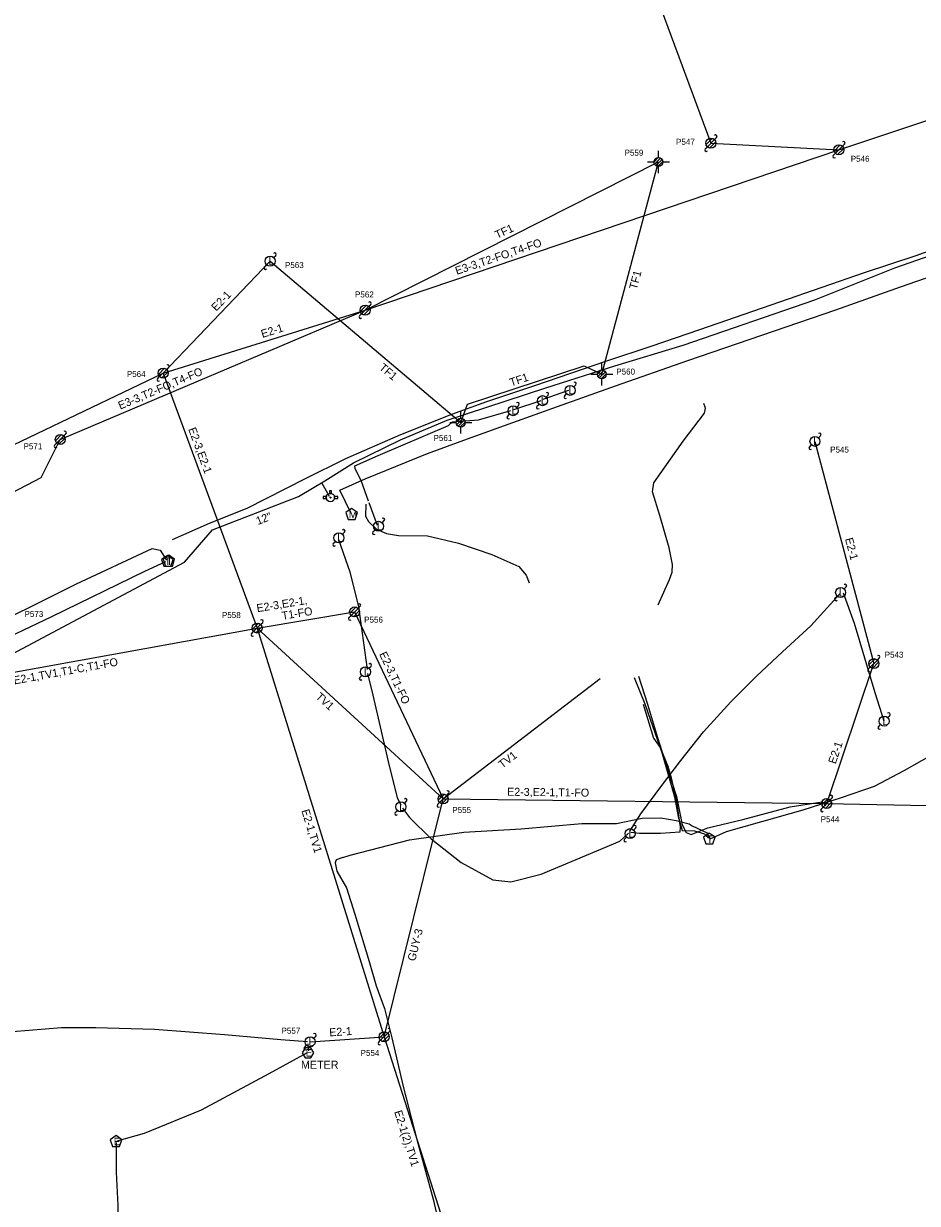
# Model space of a CAD drawing. Extents: x 1614474 to 1865144, y 1098877 to 1212550.
# Drawn here: x 1812913 to 1813359, y 1189432 to 1190021 of the extents above; entities that cross this region are included whole.
import ezdxf

# ---------------------------------------------------------------- set-up
doc = ezdxf.new("R2010")
doc.units = 0
for name, color, linetype in [('RD_EX_SU_Elec', 7, 'Continuous'), ('RD_EX_SU_H2O', 7, 'Continuous'), ('RD_EX_SU_Ovhd', 7, 'Continuous'), ('RD_EX_SU_Pole', 7, 'Continuous'), ('RD_EX_SU_Telecom', 7, 'Continuous'), ('RD_EX_SU_TX_Elec', 7, 'Continuous'), ('RD_EX_SU_TX_H2O', 7, 'Continuous'), ('RD_EX_SU_TX_Pole', 7, 'Continuous')]:
    doc.layers.add(name, color=color, linetype=linetype)

# ---------------------------------------------------------------- blocks, each defined once
blk = doc.blocks.new('SUE_PP')
at = {"layer": 'RD_EX_SU_Pole'}
for p, q in [((-2.41, -0.65), (0.65, 2.41)), ((-1.77, -1.77), (1.77, 1.77)), ((-0.65, -2.41), (2.41, 0.65)), ((1.77, 1.77), (2.83, 2.83)), ((-2.83, -2.83), (-1.77, -1.77))]:
    blk.add_line(p, q, dxfattribs=at)
blk.add_circle((0, 0), 2.5, dxfattribs=at)
for centre, start, end in [((2.3, 3.36), 315, 135), ((-2.3, -3.36), 135, 315)]:
    blk.add_arc(centre, 0.75, start, end, dxfattribs=at)
blk = doc.blocks.new('SUE_TPP')
at = {"layer": 'RD_EX_SU_Telecom'}
blk.add_lwpolyline([(0, 3), (-2.85, 0.93), (-1.76, -2.43), (1.76, -2.43), (2.85, 0.93)], close=True, dxfattribs=at)
blk.add_text('T', height=3.75, dxfattribs=at).set_placement((-1.25, -1.88))
blk = doc.blocks.new('SUE_WFH')
at = {"layer": 'RD_EX_SU_H2O'}
for p, q in [((-2.01, 0.6), (-3.65, 0.6)), ((-3.65, 0.6), (-3.65, -0.45)), ((-0.48, 3.38), (-0.48, 2.04)), ((0.57, 3.38), (-0.48, 3.38)), ((0.57, 2.02), (0.57, 3.38)), ((3.7, 0.6), (2.01, 0.6)), ((3.7, -0.45), (3.7, 0.6)), ((-3.65, -0.45), (-2.05, -0.45)), ((2.05, -0.45), (3.7, -0.45))]:
    blk.add_line(p, q, dxfattribs=at)
for radius in [2.1, 0.263]:
    blk.add_circle((0, 0), radius, dxfattribs=at)
for start, end in [(163.3387, 192.31502), (74.24552, 103.21276), (347.68498, 16.6613)]:
    blk.add_arc((0, 0), 2.1, start, end, dxfattribs=at)
blk = doc.blocks.new('SUE_WM')
at = {"layer": 'RD_EX_SU_H2O'}
blk.add_lwpolyline([(0, 3.05), (-2.9, 0.94), (-1.79, -2.47), (1.79, -2.47), (2.9, 0.94)], close=True, dxfattribs=at)
blk.add_text('M', height=3.75, dxfattribs=at).set_placement((-1.43, -1.88))

msp = doc.modelspace()

# ---------------------------------------------------------------- linework, layer by layer
at = {"layer": 'RD_EX_SU_Elec'}
for p, q in [((1813172.2, 1189833.77), (1813184.99, 1189838.24)), ((1813157.49, 1189828.68), (1813171.11, 1189833.14)), ((1813084.97, 1189782.12), (1813089.24, 1189770.86)), ((1813054.52, 1189511.62), (1813054.88, 1189508.19))]:
    msp.add_line(p, q, dxfattribs=at)
for points in [[(1813084.8, 1189782.72), (1813081.16, 1189793.2), (1813078.24, 1189799.02), (1813078.11, 1189800.47), (1813089.66, 1189805.56), (1813124.92, 1189820.6), (1813126.88, 1189822.42), (1813139.84, 1189823.39), (1813156.03, 1189828.18)], [(1813229.62, 1189731.04), (1813235.19, 1189743.69), (1813236.63, 1189747.25), (1813236.84, 1189751.08), (1813235.18, 1189759.44), (1813230.46, 1189775.63), (1813226.78, 1189787.46), (1813227.5, 1189791.98), (1813242.03, 1189812.74), (1813252.8, 1189826.76), (1813253.21, 1189829.19), (1813252.42, 1189831.68)], [(1813083.58, 1189781.3), (1813083.29, 1189775.35), (1813084.79, 1189772.68), (1813088.83, 1189768.74), (1813093.82, 1189766.63), (1813099.9, 1189765.58), (1813114.37, 1189765.46), (1813129.83, 1189761.79), (1813146.53, 1189756.21), (1813159.94, 1189750.16), (1813163.6, 1189745.85), (1813165.14, 1189741.93)], [(1813069.9, 1189763.7), (1813075.59, 1189747.53), (1813079.94, 1189730.01), (1813082.4, 1189712.02), (1813084.12, 1189698.67)], [(1813215.48, 1189617.9), (1813220.92, 1189626.65), (1813231.43, 1189640.69), (1813240.87, 1189653.16), (1813252.21, 1189667.55), (1813265.87, 1189682.5), (1813278.75, 1189695.4), (1813291.8, 1189707.54), (1813305.86, 1189720.44), (1813320.47, 1189736.69)], [(1813322.09, 1189736.98), (1813327.51, 1189721.81), (1813337.79, 1189687.25), (1813342.36, 1189673.09)], [(1813084.31, 1189696.75), (1813087, 1189685.89), (1813091.12, 1189667.82), (1813095.19, 1189650.6), (1813099.16, 1189634.7), (1813100.95, 1189630.93)], [(1813219.74, 1189695.38), (1813224.14, 1189681.94), (1813229.28, 1189664.63), (1813234.01, 1189650.08), (1813238.7, 1189635.2), (1813241.53, 1189621), (1813243.55, 1189617.16), (1813246.01, 1189616.2), (1813254.4, 1189619.51), (1813271.84, 1189623.68), (1813295.49, 1189630.04), (1813311.6, 1189632.56), (1813313.32, 1189630.61)], [(1813222.12, 1189681.31), (1813227.35, 1189664.46), (1813230.57, 1189659.71), (1813234.5, 1189650.34), (1813236.05, 1189644.54), (1813238.7, 1189632.16), (1813240.56, 1189620.13), (1813240.51, 1189617.37), (1813230.72, 1189616.67), (1813220.31, 1189616.77), (1813215.93, 1189617.17)], [(1813101.94, 1189629.37), (1813105.36, 1189624.7), (1813116.25, 1189614.02), (1813131.09, 1189602.33), (1813146.98, 1189593.61), (1813156.06, 1189592.63), (1813171.1, 1189596.36), (1813199.01, 1189608.09), (1813210.42, 1189612.97), (1813214.78, 1189616.97)], [(1812867.17, 1189511.33), (1812869.82, 1189511.09), (1812890.43, 1189516.51), (1812931.39, 1189519.83), (1812948.66, 1189519.83), (1812977.88, 1189518.89), (1813012.86, 1189516.32), (1813041.01, 1189513.73), (1813054.44, 1189512.83)], [(1812959.31, 1189463.15), (1812972.97, 1189467.02), (1813001.48, 1189478.6), (1813035.3, 1189496.77), (1813054.4, 1189507.35)], [(1812958.79, 1189462.41), (1812958.8, 1189447.44), (1812959.6, 1189430.8), (1812958.07, 1189367), (1812957.55, 1189348.86), (1812956.38, 1189299.52), (1812957.5, 1189269.31), (1812955.97, 1189255.72), (1812952.75, 1189234.62)]]:
    msp.add_lwpolyline(points, dxfattribs=at)
for points in [[(1813057.55, 1189507.16), (1813056.11, 1189509.66), (1813053.22, 1189509.66), (1813051.78, 1189507.16), (1813053.22, 1189504.66), (1813056.11, 1189504.66)], [(1812958.73, 1189465.85), (1812955.83, 1189463.74), (1812956.93, 1189460.33), (1812960.52, 1189460.33), (1812961.63, 1189463.74)]]:
    msp.add_lwpolyline(points, close=True, dxfattribs=at)
at = {"layer": 'RD_EX_SU_H2O'}
msp.add_line((1813061.4, 1189792.09), (1813065.25, 1189785.38), dxfattribs=at)
for points in [[(1813049.93, 1189785.18), (1813062.98, 1189793.04), (1813077.41, 1189801.91), (1813100.8, 1189813.52), (1813124.24, 1189823.21), (1813173.48, 1189839.48), (1813207.95, 1189850.5), (1813242.12, 1189860.74), (1813307.93, 1189883.34), (1813347.93, 1189899.33), (1813402.79, 1189918.54), (1813471.7, 1189944.89), (1813528.83, 1189966.2), (1813605.69, 1189995.43), (1813667.12, 1190020.2)], [(1813076.17, 1189776.71), (1813070.48, 1189788.22), (1813083.19, 1189794.03), (1813114.42, 1189806.57), (1813134.39, 1189813.94), (1813156.92, 1189822.09), (1813179.27, 1189830.15), (1813208.26, 1189840.49), (1813244.46, 1189853.13), (1813287.8, 1189867.84), (1813318.33, 1189878.33), (1813350.77, 1189889.9), (1813379.04, 1189899.78), (1813403.28, 1189907.87), (1813412.45, 1189891.9), (1813420.34, 1189875.71), (1813427, 1189862.13)], [(1812530.07, 1189435.57), (1812805.53, 1189652.49), (1812993.01, 1189752.31), (1813006.84, 1189768.49), (1813049.93, 1189785.18)]]:
    msp.add_lwpolyline(points, dxfattribs=at)
at = {"layer": 'RD_EX_SU_Ovhd'}
for p, q in [((1813205.47, 1190098.07), (1813255.96, 1189961.68)), ((1813319.93, 1189958.41), (1813557.25, 1190037.52)), ((1813083.19, 1189878.25), (1813319.93, 1189958.41)), ((1813255.96, 1189961.68), (1813319.93, 1189958.41)), ((1813083.19, 1189878.25), (1813229.74, 1189952.29)), ((1813201.45, 1189846.2), (1813229.74, 1189952.29)), ((1812982.29, 1189846.79), (1813035.7, 1189902.73)), ((1813035.7, 1189902.73), (1813130.96, 1189822.07)), ((1812930.87, 1189813.64), (1813083.19, 1189878.25)), ((1812982.29, 1189846.79), (1813083.19, 1189878.25)), ((1812808.56, 1189763.74), (1812982.29, 1189846.79)), ((1812982.29, 1189846.79), (1813029.22, 1189719.4)), ((1813307.96, 1189812.69), (1813337.35, 1189701.63)), ((1813029.22, 1189719.4), (1813077.95, 1189727.45)), ((1813077.95, 1189727.45), (1813122.17, 1189634)), ((1812850.33, 1189686.85), (1813029.22, 1189719.4)), ((1813029.22, 1189719.4), (1813122.17, 1189634)), ((1813029.22, 1189719.4), (1813092.68, 1189515.17)), ((1813313.8, 1189631.73), (1813337.35, 1189701.63)), ((1813122.17, 1189634), (1813200.58, 1189694.11)), ((1813092.68, 1189515.17), (1813122.17, 1189634)), ((1813122.17, 1189634), (1813313.8, 1189631.73)), ((1813313.8, 1189631.73), (1813457.23, 1189628.94)), ((1813055.69, 1189512.68), (1813092.68, 1189515.17)), ((1813092.68, 1189515.17), (1813158.57, 1189308.63))]:
    msp.add_line(p, q, dxfattribs=at)
for points in [[(1813130.96, 1189822.07), (1813134.32, 1189831.24), (1813192.68, 1189850.48), (1813201.45, 1189846.2)], [(1812780.79, 1189733.02), (1812803.04, 1189732.83), (1812921.31, 1189794.68), (1812930.87, 1189813.64)]]:
    msp.add_lwpolyline(points, dxfattribs=at)
at = {"layer": 'RD_EX_SU_Pole'}
for p, q in [((1813253.55, 1189961.03), (1813256.61, 1189964.09)), ((1813254.2, 1189959.91), (1813257.73, 1189963.44)), ((1813257.73, 1189963.44), (1813258.79, 1189964.5)), ((1813229.74, 1189954.51), (1813229.74, 1189957.82)), ((1813253.13, 1189958.85), (1813254.2, 1189959.91)), ((1813255.32, 1189959.26), (1813258.38, 1189962.32)), ((1813317.52, 1189957.76), (1813320.58, 1189960.83)), ((1813318.17, 1189956.64), (1813321.7, 1189960.18)), ((1813319.29, 1189956), (1813322.35, 1189959.06)), ((1813321.7, 1189960.18), (1813322.76, 1189961.24)), ((1813224.22, 1189952.29), (1813227.53, 1189952.29)), ((1813227.53, 1189952.43), (1813229.62, 1189954.5)), ((1813227.78, 1189951.26), (1813230.78, 1189954.25)), ((1813228.43, 1189950.5), (1813231.54, 1189953.6)), ((1813229.44, 1189950.1), (1813231.94, 1189952.59)), ((1813231.96, 1189952.29), (1813235.27, 1189952.29)), ((1813317.11, 1189955.58), (1813318.17, 1189956.64)), ((1813229.74, 1189946.76), (1813229.74, 1189950.07)), ((1813037.47, 1189904.49), (1813038.53, 1189905.56)), ((1813032.87, 1189899.9), (1813033.93, 1189900.96)), ((1813080.77, 1189877.6), (1813083.83, 1189880.66)), ((1813084.95, 1189880.02), (1813086.01, 1189881.08)), ((1813080.36, 1189875.42), (1813081.42, 1189876.48)), ((1813081.42, 1189876.48), (1813084.95, 1189880.02)), ((1813082.54, 1189875.83), (1813085.6, 1189878.89)), ((1813201.45, 1189848.42), (1813201.45, 1189851.73)), ((1812979.87, 1189846.15), (1812982.93, 1189849.21)), ((1812980.52, 1189845.03), (1812984.05, 1189848.56)), ((1812981.64, 1189844.38), (1812984.7, 1189847.44)), ((1812984.05, 1189848.56), (1812985.11, 1189849.62)), ((1813195.93, 1189846.2), (1813199.24, 1189846.2)), ((1813199.24, 1189846.34), (1813201.33, 1189848.42)), ((1813199.49, 1189845.17), (1813202.49, 1189848.16)), ((1813200.14, 1189844.41), (1813203.25, 1189847.51)), ((1813201.15, 1189844.01), (1813203.65, 1189846.5)), ((1813203.67, 1189846.2), (1813206.98, 1189846.2)), ((1812979.46, 1189843.97), (1812980.52, 1189845.03)), ((1813187.4, 1189839.93), (1813188.46, 1189840.99)), ((1813201.45, 1189840.68), (1813201.45, 1189843.99)), ((1813173.61, 1189834.79), (1813174.67, 1189835.85)), ((1813182.81, 1189835.33), (1813183.87, 1189836.39)), ((1813130.96, 1189824.28), (1813130.96, 1189827.59)), ((1813158.89, 1189829.76), (1813159.95, 1189830.83)), ((1813169.01, 1189830.2), (1813170.07, 1189831.26)), ((1813125.44, 1189822.07), (1813128.75, 1189822.07)), ((1813128.75, 1189822.2), (1813130.84, 1189824.28)), ((1813129, 1189821.04), (1813132, 1189824.03)), ((1813129.66, 1189820.28), (1813132.76, 1189823.37)), ((1813130.66, 1189819.87), (1813133.16, 1189822.36)), ((1813133.18, 1189822.07), (1813136.49, 1189822.07)), ((1813154.29, 1189825.17), (1813155.35, 1189826.23)), ((1812928.45, 1189813), (1812931.51, 1189816.06)), ((1812932.64, 1189815.41), (1812933.7, 1189816.47)), ((1813130.96, 1189816.54), (1813130.96, 1189819.85)), ((1812928.04, 1189810.81), (1812929.1, 1189811.87)), ((1812929.1, 1189811.87), (1812932.64, 1189815.41)), ((1812930.22, 1189811.23), (1812933.28, 1189814.29)), ((1813305.14, 1189809.86), (1813306.2, 1189810.92)), ((1813309.73, 1189814.46), (1813310.79, 1189815.52)), ((1813087.09, 1189767.42), (1813088.15, 1189768.48)), ((1813091.68, 1189772.01), (1813092.74, 1189773.07)), ((1813067.26, 1189761.66), (1813068.32, 1189762.72)), ((1813071.86, 1189766.26), (1813072.92, 1189767.32)), ((1813322.55, 1189738.94), (1813323.61, 1189740)), ((1813317.95, 1189734.35), (1813319.01, 1189735.41)), ((1813075.54, 1189726.8), (1813078.6, 1189729.86)), ((1813076.18, 1189725.68), (1813079.72, 1189729.22)), ((1813077.3, 1189725.04), (1813080.37, 1189728.1)), ((1813079.72, 1189729.22), (1813080.78, 1189730.28)), ((1813026.8, 1189718.75), (1813029.86, 1189721.82)), ((1813030.98, 1189721.17), (1813032.04, 1189722.23)), ((1813075.12, 1189724.62), (1813076.18, 1189725.68)), ((1813026.39, 1189716.57), (1813027.45, 1189717.63)), ((1813027.45, 1189717.63), (1813030.98, 1189721.17)), ((1813028.57, 1189716.99), (1813031.63, 1189720.05)), ((1813085.1, 1189699.3), (1813086.16, 1189700.36)), ((1813080.5, 1189694.7), (1813081.56, 1189695.76)), ((1813344.25, 1189674.69), (1813345.31, 1189675.75)), ((1813339.65, 1189670.09), (1813340.71, 1189671.15)), ((1813102.84, 1189631.81), (1813103.9, 1189632.87)), ((1813119.75, 1189633.35), (1813122.82, 1189636.41)), ((1813120.4, 1189632.23), (1813123.94, 1189635.76)), ((1813121.52, 1189631.58), (1813124.58, 1189634.64)), ((1813123.94, 1189635.76), (1813125, 1189636.82)), ((1813311.38, 1189631.08), (1813314.44, 1189634.14)), ((1813312.03, 1189629.96), (1813315.56, 1189633.5)), ((1813315.56, 1189633.5), (1813316.62, 1189634.56)), ((1813098.24, 1189627.22), (1813099.3, 1189628.28)), ((1813119.34, 1189631.17), (1813120.4, 1189632.23)), ((1813310.97, 1189628.9), (1813312.03, 1189629.96)), ((1813313.15, 1189629.31), (1813316.21, 1189632.38)), ((1813217.33, 1189618.45), (1813218.39, 1189619.51)), ((1813212.74, 1189613.85), (1813213.8, 1189614.91)), ((1813057.45, 1189514.45), (1813058.52, 1189515.51)), ((1813090.27, 1189514.52), (1813093.33, 1189517.58)), ((1813090.92, 1189513.4), (1813094.45, 1189516.93)), ((1813092.04, 1189512.75), (1813095.1, 1189515.81)), ((1813094.45, 1189516.93), (1813095.51, 1189518)), ((1813052.86, 1189509.85), (1813053.92, 1189510.92)), ((1813089.86, 1189512.34), (1813090.92, 1189513.4))]:
    msp.add_line(p, q, dxfattribs=at)
for centre, radius in [((1813255.96, 1189961.68), 2.5), ((1813319.93, 1189958.41), 2.5), ((1813229.74, 1189952.29), 2.22), ((1813035.7, 1189902.73), 2.5), ((1813083.19, 1189878.25), 2.5), ((1812982.29, 1189846.79), 2.5), ((1813201.45, 1189846.2), 2.22), ((1813185.63, 1189838.16), 2.5), ((1813171.84, 1189833.02), 2.5), ((1813157.12, 1189828), 2.5), ((1813130.96, 1189822.07), 2.22), ((1812930.87, 1189813.64), 2.5), ((1813307.96, 1189812.69), 2.5), ((1813089.91, 1189770.24), 2.5), ((1813070.09, 1189764.49), 2.5), ((1813320.78, 1189737.17), 2.5), ((1813077.95, 1189727.45), 2.5), ((1813029.22, 1189719.4), 2.5), ((1813083.33, 1189697.53), 2.5), ((1813342.48, 1189672.92), 2.5), ((1813122.17, 1189634), 2.5), ((1813313.8, 1189631.73), 2.5), ((1813101.07, 1189630.05), 2.5), ((1813215.56, 1189616.68), 2.5), ((1813055.69, 1189512.68), 2.5), ((1813092.68, 1189515.17), 2.5)]:
    msp.add_circle(centre, radius, dxfattribs=at)
for centre, start, end in [((1813258.26, 1189965.03), 315, 135), ((1813253.66, 1189958.32), 135, 315), ((1813322.23, 1189961.77), 315, 135), ((1813317.64, 1189955.05), 135, 315), ((1813038, 1189906.09), 315, 135), ((1813033.4, 1189899.37), 135, 315), ((1813085.48, 1189881.61), 315, 135), ((1813080.89, 1189874.89), 135, 315), ((1812984.58, 1189850.15), 315, 135), ((1812979.99, 1189843.44), 135, 315), ((1813187.93, 1189841.52), 315, 135), ((1813174.14, 1189836.38), 315, 135), ((1813183.34, 1189834.8), 135, 315), ((1813159.42, 1189831.36), 315, 135), ((1813169.54, 1189829.66), 135, 315), ((1813154.82, 1189824.64), 135, 315), ((1812933.17, 1189817), 315, 135), ((1813310.26, 1189816.05), 315, 135), ((1812928.57, 1189810.28), 135, 315), ((1813305.67, 1189809.33), 135, 315), ((1813092.21, 1189773.6), 315, 135), ((1813072.39, 1189767.85), 315, 135), ((1813087.62, 1189766.89), 135, 315), ((1813067.79, 1189761.13), 135, 315), ((1813323.08, 1189740.53), 315, 135), ((1813318.48, 1189733.82), 135, 315), ((1813080.25, 1189730.81), 315, 135), ((1813031.51, 1189722.76), 315, 135), ((1813075.65, 1189724.09), 135, 315), ((1813026.92, 1189716.04), 135, 315), ((1813085.63, 1189700.89), 315, 135), ((1813081.03, 1189694.17), 135, 315), ((1813344.78, 1189676.28), 315, 135), ((1813340.18, 1189669.56), 135, 315), ((1813103.37, 1189633.4), 315, 135), ((1813124.47, 1189637.35), 315, 135), ((1813316.09, 1189635.09), 315, 135), ((1813098.77, 1189626.69), 135, 315), ((1813119.87, 1189630.64), 135, 315), ((1813311.5, 1189628.37), 135, 315), ((1813217.86, 1189620.04), 315, 135), ((1813213.27, 1189613.32), 135, 315), ((1813057.99, 1189516.04), 315, 135), ((1813094.98, 1189518.53), 315, 135), ((1813053.39, 1189509.32), 135, 315), ((1813090.39, 1189511.81), 135, 315)]:
    msp.add_arc(centre, 0.75, start, end, dxfattribs=at)
at = {"layer": 'RD_EX_SU_Telecom'}
for points in [[(1812986.98, 1189763.67), (1813005.44, 1189771.75), (1813024.19, 1189779.33), (1813053.31, 1189794.14), (1813073.59, 1189804.15), (1813101.03, 1189816.06), (1813126.47, 1189826.28), (1813144.04, 1189832.67), (1813167.98, 1189840.52), (1813203.88, 1189852.88), (1813226.05, 1189860.24), (1813250.43, 1189868.52), (1813290.34, 1189882.36), (1813332.67, 1189897.04), (1813358.52, 1189905.57), (1813386.31, 1189915.56), (1813426.66, 1189930.34), (1813454.68, 1189941.28), (1813481.84, 1189951.54)], [(1813255.57, 1189614.06), (1813263.68, 1189617.82), (1813281.32, 1189622.74), (1813302.06, 1189628.54), (1813321.29, 1189634.79), (1813337.62, 1189640.37), (1813352.54, 1189648.16), (1813361.42, 1189653.14), (1813374.32, 1189660.59), (1813389.71, 1189667.88), (1813402.08, 1189676.45), (1813413.44, 1189689.97), (1813422.05, 1189705.47), (1813428.42, 1189717.32), (1813439.68, 1189738.07), (1813441.87, 1189744.68), (1813447.8, 1189752.78), (1813453.72, 1189763.94), (1813462.54, 1189781.61), (1813467.31, 1189791.17), (1813476.35, 1189813.22), (1813477.46, 1189816.76)], [(1812849.23, 1189687.67), (1812849.3, 1189694.68), (1812885.98, 1189715.21), (1812939.04, 1189741.55), (1812976.77, 1189759.12), (1812980.75, 1189758.26), (1812983.89, 1189753.32)], [(1812894.35, 1189709.92), (1812926.56, 1189725.13), (1812973.09, 1189747.78), (1812983.57, 1189752.66)], [(1813217.58, 1189694.67), (1813222.96, 1189681.58), (1813225.76, 1189673.3), (1813231.41, 1189657.2), (1813237.76, 1189635.04), (1813239.66, 1189625.28), (1813241.65, 1189618.28), (1813247.68, 1189618.06), (1813252.72, 1189616.54), (1813254.76, 1189614.41)], [(1813072.08, 1189604.82), (1813075.74, 1189605.86), (1813105.32, 1189613.62), (1813132.49, 1189617.34), (1813161.17, 1189619.11), (1813191.49, 1189621.77), (1813208.82, 1189621.71), (1813221.63, 1189624.45), (1813230.91, 1189624.52), (1813238.67, 1189623.29), (1813245.1, 1189621.6), (1813246.67, 1189620.61), (1813254.11, 1189617.09), (1813255.18, 1189614.41)], [(1813072.08, 1189604.82), (1813068.71, 1189603.57), (1813068.2, 1189602.09), (1813069.12, 1189597.9), (1813073.8, 1189589.64), (1813078.08, 1189576.44), (1813085.26, 1189552.84), (1813088.75, 1189540.66), (1813092.82, 1189529.22), (1813096.58, 1189514.62), (1813102.16, 1189490.33), (1813109.1, 1189463.84), (1813117.24, 1189434.02), (1813124.01, 1189404.62), (1813130.86, 1189382.63), (1813134.55, 1189369.62), (1813138.23, 1189358.5), (1813144.63, 1189339.05), (1813152.21, 1189319.35), (1813156.72, 1189309.04)]]:
    msp.add_lwpolyline(points, dxfattribs=at)

# ---------------------------------------------------------------- block references
at = {"layer": 'RD_EX_SU_H2O'}
for name, p in [('SUE_WFH', (1813065.86, 1189784.58)), ('SUE_WM', (1813076.45, 1189776.16))]:
    msp.add_blockref(name, p, dxfattribs=at)
at = {"layer": 'RD_EX_SU_Pole'}
msp.add_blockref('SUE_PP', (1813337.35, 1189701.63), dxfattribs=at)
at = {"layer": 'RD_EX_SU_Telecom'}
for p in [(1812984.36, 1189752.72), (1812985.13, 1189752.83), (1813255.17, 1189613.94)]:
    msp.add_blockref('SUE_TPP', p, dxfattribs=at)

# ---------------------------------------------------------------- texts
at = {"layer": 'RD_EX_SU_Elec'}
for p in [(1813053.5, 1189505.28), (1812957.56, 1189460.93)]:
    msp.add_text('E', height=3.75, dxfattribs=at).set_placement(p)
at = {"layer": 'RD_EX_SU_Ovhd'}
for s, rotation, p in [('TF1', 24.84961, (1813149.17, 1189913.8)), ('E3-3,T2-FO,T4-FO', 18.70624, (1813129, 1189895.87)), ('TF1', 75.06892, (1813218.89, 1189888.29)), ('E2-1', 46.32032, (1813008.79, 1189877.44)), ('E2-1', 17.31375, (1813031.87, 1189864.35)), ('TF1', 319.74584, (1813089.86, 1189849)), ('E3-3,T2-FO,T4-FO', 22.98412, (1812960.8, 1189828.52)), ('TF1', 18.90213, (1813156.18, 1189840.06)), ('E2-3,E2-1', 290.22315, (1812994.73, 1189818.8)), ('E2-1', 284.82013, (1813322.93, 1189763.96)), ('E2-3,E2-1,', 9.37901, (1813029.29, 1189727.29)), ('T1-FO', 9.37901, (1813041.88, 1189723.52)), ('E2-3,E2-1,TV1,T1-C,T1-FO', 10.31357, (1812895.31, 1189688.93)), ('E2-3,T1-FO', 295.32058, (1813090.1, 1189706.44)), ('TV1', 317.42312, (1813058.18, 1189684.64)), ('TV1', 37.47685, (1813151.7, 1189649.07)), ('E2-1', 71.38005, (1813318.25, 1189651.2)), ('E2-3,E2-1,T1-FO', 359.32255, (1813154.09, 1189635.62)), ('E2-1,TV1', 287.26338, (1813051.29, 1189628.16)), ('GUY-3', 76.06492, (1813108.18, 1189552.71)), ('E2-1', 3.84154, (1813065.39, 1189515.34)), ('E2-1(2),TV1', 287.69178, (1813097.65, 1189477.7))]:
    msp.add_text(s, height=4, rotation=rotation, dxfattribs=at).set_placement(p)
at = {"layer": 'RD_EX_SU_Pole'}
for p in [(1813034.84, 1189900.73), (1813184.77, 1189836.16), (1813170.98, 1189831.02), (1813156.26, 1189826), (1813307.1, 1189810.69), (1813089.05, 1189768.24), (1813069.23, 1189762.49), (1813319.92, 1189735.17), (1813082.47, 1189695.53), (1813341.62, 1189670.92), (1813100.21, 1189628.05), (1813214.7, 1189614.68), (1813054.82, 1189510.68)]:
    msp.add_text('L', height=4, dxfattribs=at).set_placement(p)
at = {"layer": 'RD_EX_SU_TX_Elec'}
msp.add_text('METER', height=4, dxfattribs=at).set_placement((1813051.15, 1189499.2))
at = {"layer": 'RD_EX_SU_TX_H2O'}
msp.add_text('12"', height=4, rotation=21.17067, dxfattribs=at).set_placement((1813029.59, 1189770.86))
at = {"layer": 'RD_EX_SU_TX_Pole'}
for s, p in [('P547', (1813238.55, 1189960.86)), ('P559', (1813212.83, 1189955.41)), ('P546', (1813325.84, 1189952.38)), ('P563', (1813043.14, 1189899.28)), ('P562', (1813078.13, 1189884.59)), ('P564', (1812964.13, 1189844.84)), ('P560', (1813208.68, 1189846.06)), ('P561', (1813117.38, 1189812.88)), ('P571', (1812912.51, 1189808.74)), ('P545', (1813315.54, 1189807.09)), ('P573', (1812913, 1189724.94)), ('P558', (1813011.66, 1189724.39)), ('P556', (1813082.69, 1189722.09)), ('P543', (1813342.8, 1189704.59)), ('P555', (1813126.75, 1189626.99)), ('P544', (1813310.8, 1189622.38)), ('P557', (1813041.41, 1189516.71)), ('P554', (1813080.93, 1189505.63))]:
    msp.add_text(s, height=3, dxfattribs=at).set_placement(p)

doc.saveas('drawing.dxf')
